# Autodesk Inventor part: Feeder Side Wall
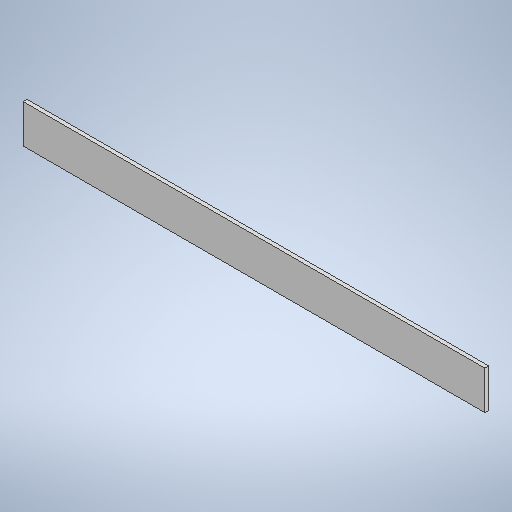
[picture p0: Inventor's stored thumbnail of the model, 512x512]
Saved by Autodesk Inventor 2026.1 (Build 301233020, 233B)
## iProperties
Created: 2026-11
Part Number: Feeder Side Wall
Material: Generic
Document SubType Name: Modeling
Designer: hp
Density: 1 g/cm^3
Appearance: Default
Author: hp
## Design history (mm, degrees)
sketch "Sketch1"
  geometry: L1 (0, 0)-(600, 0); L2 (600, 0)-(600, 50); L3 (600, 50)-(0, 50); L4 (0, 50)-(0, 0)
  constraints: 8 end point, 2 parallel, 1 horizontal, 1 perpendicular
  dimensions: "d0" = 600 distance of L3.end L2.end; "d1" = 50 distance of L2.end L1.end
extrude "Extrusion1" new body sketch "Sketch1" distance "d2" = 5; taper "d3" = 0 deg
body "Solid1"
